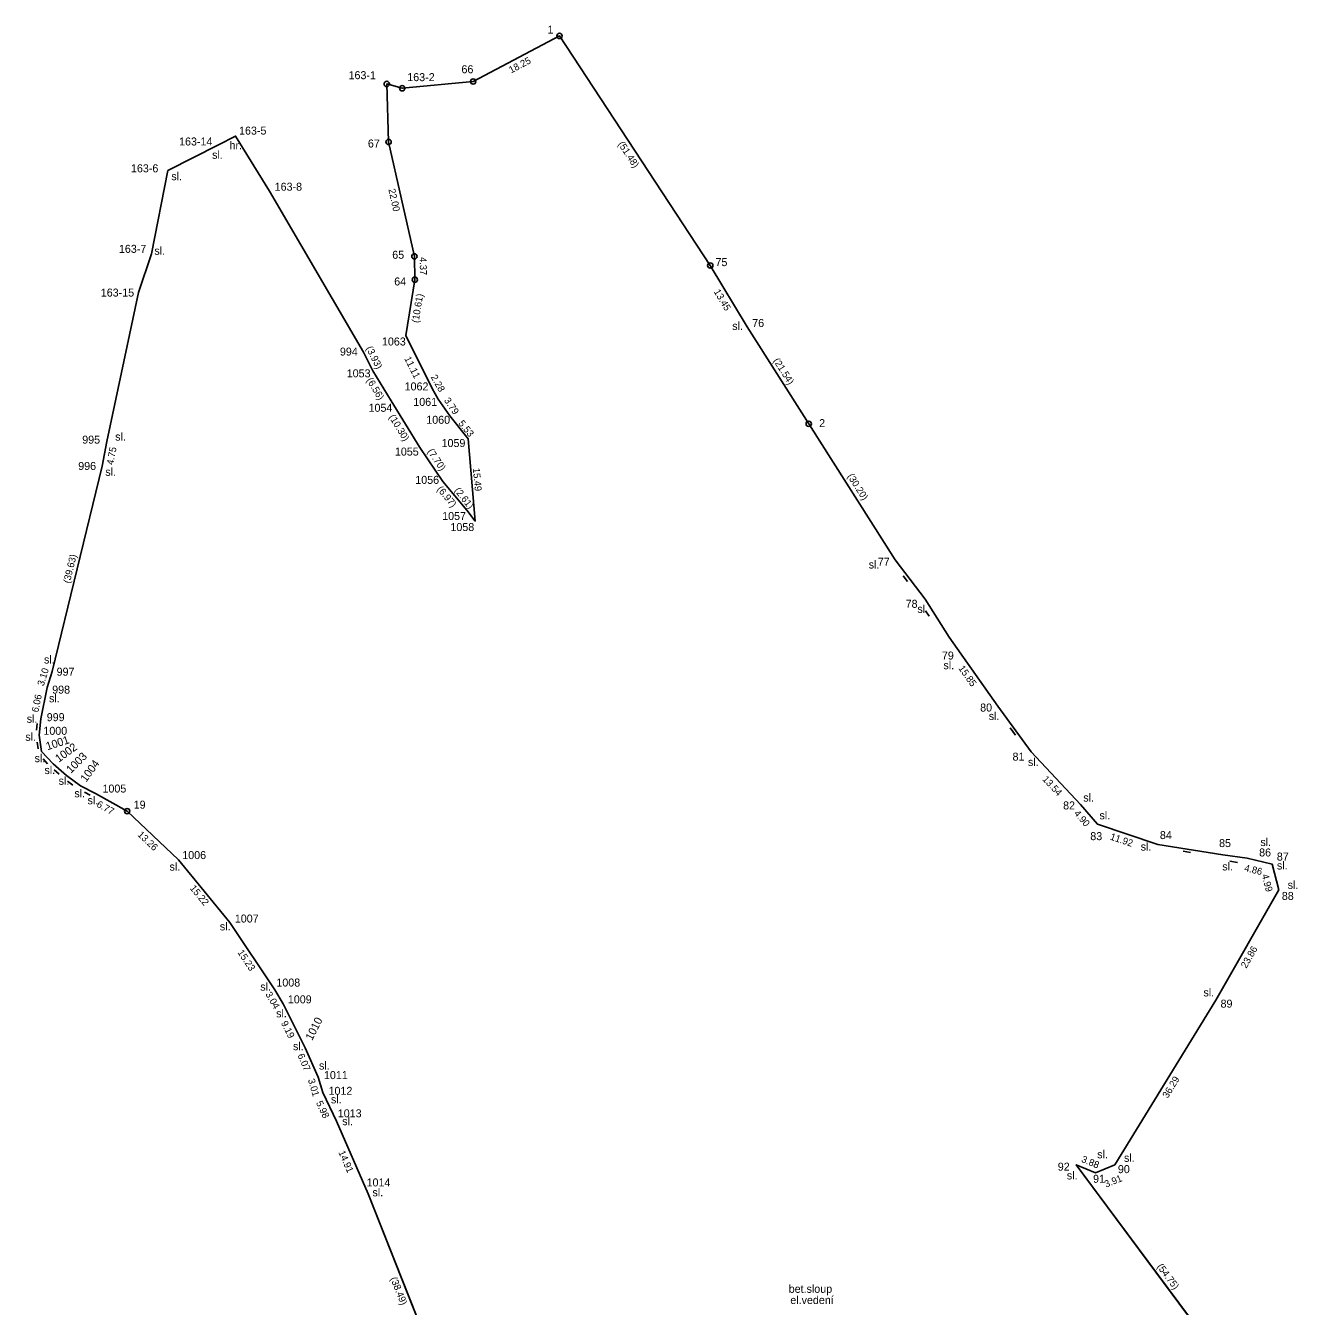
# Model space of a CAD drawing. Extents: x -555170 to -550532, y -1039598 to -1034701.
# Drawn here: x -553164.9 to -552926.5, y -1037844.3 to -1037604.2 of the extents above; entities that cross this region are included whole.
import ezdxf

# ---------------------------------------------------------------- set-up
doc = ezdxf.new("R2010")
doc.units = 0
for name, color, linetype in [('Vrstva 10', 7, 'Continuous'), ('Vrstva 40', 7, 'Continuous'), ('Vrstva 43', 7, 'Continuous'), ('Vrstva 48', 7, 'Continuous')]:
    doc.layers.add(name, color=color, linetype=linetype)

msp = doc.modelspace()

# ---------------------------------------------------------------- linework, layer by layer
at = {"layer": 'Vrstva 10'}
for p, q in [((-553000.41, -1037707.36), (-552999.6, -1037708.41)), ((-552996.24, -1037713.94), (-552995.52, -1037714.93)), ((-553162.87, -1037736.3), (-553162.77, -1037735.08)), ((-552980.37, -1037735.85), (-552979.35, -1037737.26)), ((-553162.6, -1037739.81), (-553162.77, -1037738.59)), ((-553160.85, -1037742.63), (-553161.65, -1037741.7)), ((-553158.66, -1037744.57), (-553159.59, -1037743.77)), ((-553156.08, -1037746.61), (-553157.06, -1037745.87)), ((-553152.81, -1037748.51), (-553153.89, -1037747.93)), ((-552947.95, -1037758.98), (-552946.57, -1037759.25)), ((-552937.73, -1037761.11), (-552939.17, -1037760.84))]:
    msp.add_line(p, q, dxfattribs=at)
at = {"layer": 'Vrstva 40'}
for p, q in [((-553064.84, -1037606.16), (-553081.02, -1037614.69)), ((-553036.58, -1037649.19), (-553064.84, -1037606.16)), ((-553094.34, -1037615.96), (-553097.23, -1037615.16)), ((-553097.23, -1037615.16), (-553096.88, -1037626.02)), ((-553081.02, -1037614.69), (-553094.34, -1037615.96)), ((-553125.58, -1037624.92), (-553128.8, -1037626.55)), ((-553119.24, -1037635.27), (-553125.58, -1037624.92)), ((-553128.8, -1037626.55), (-553138.25, -1037631.4)), ((-553096.88, -1037626.02), (-553092.05, -1037647.49)), ((-553138.25, -1037631.4), (-553141.35, -1037647.01)), ((-553101.57, -1037665.44), (-553119.24, -1037635.27)), ((-553141.35, -1037647.01), (-553143.76, -1037654.28)), ((-553092.05, -1037647.49), (-553091.97, -1037651.86)), ((-553029.69, -1037660.7), (-553036.58, -1037649.19)), ((-553091.97, -1037651.86), (-553093.67, -1037662.33)), ((-553143.76, -1037654.28), (-553149.7, -1037682.18)), ((-553018.13, -1037678.87), (-553029.69, -1037660.7)), ((-553093.67, -1037662.33), (-553088.69, -1037672.27)), ((-553099.81, -1037668.95), (-553101.57, -1037665.44)), ((-553096.39, -1037674.55), (-553099.81, -1037668.95)), ((-553088.69, -1037672.27), (-553087.56, -1037674.26)), ((-553091.01, -1037683.33), (-553096.39, -1037674.55)), ((-553087.56, -1037674.26), (-553085.43, -1037677.4)), ((-553085.43, -1037677.4), (-553081.94, -1037681.68)), ((-553001.91, -1037704.35), (-553018.13, -1037678.87)), ((-553149.7, -1037682.18), (-553150.56, -1037686.84)), ((-553086.69, -1037689.7), (-553091.01, -1037683.33)), ((-553081.94, -1037681.68), (-553080.63, -1037697.11)), ((-553150.56, -1037686.84), (-553159.95, -1037725.34)), ((-553082.23, -1037695.05), (-553086.69, -1037689.7)), ((-553080.63, -1037697.11), (-553082.23, -1037695.05)), ((-552996.27, -1037711.74), (-553001.91, -1037704.35)), ((-552991.81, -1037718.9), (-552996.27, -1037711.74)), ((-552982.64, -1037731.83), (-552991.81, -1037718.9)), ((-553159.95, -1037725.34), (-553160.87, -1037728.3)), ((-553160.87, -1037728.3), (-553162.1, -1037734.2)), ((-552976.44, -1037740.39), (-552982.64, -1037731.83)), ((-553162.1, -1037734.2), (-553162.4, -1037737.27)), ((-553162.4, -1037737.27), (-553161.93, -1037740.33)), ((-553161.93, -1037740.33), (-553159.79, -1037742.65)), ((-552967.16, -1037750.24), (-552976.44, -1037740.39)), ((-553159.79, -1037742.65), (-553157.27, -1037744.81)), ((-553157.27, -1037744.81), (-553154.67, -1037746.73)), ((-553154.67, -1037746.73), (-553151.83, -1037748.2)), ((-553151.83, -1037748.2), (-553145.9, -1037751.5)), ((-552963.99, -1037753.94), (-552967.16, -1037750.24)), ((-553145.9, -1037751.5), (-553136.29, -1037760.64)), ((-552952.7, -1037757.75), (-552963.99, -1037753.94)), ((-552940.48, -1037759.68), (-552952.7, -1037757.75)), ((-552935.91, -1037760.31), (-552940.48, -1037759.68)), ((-552931.21, -1037761.44), (-552935.91, -1037760.31)), ((-553136.29, -1037760.64), (-553126.62, -1037772.37)), ((-552929.97, -1037766.27), (-552931.21, -1037761.44)), ((-552941.8, -1037786.93), (-552929.97, -1037766.27)), ((-553126.62, -1037772.37), (-553118.18, -1037785.01)), ((-553118.18, -1037785.01), (-553116.65, -1037787.63)), ((-553116.65, -1037787.63), (-553112.53, -1037795.84)), ((-552960.76, -1037817.81), (-552941.8, -1037786.93)), ((-553112.53, -1037795.84), (-553110.07, -1037801.39)), ((-553110.07, -1037801.39), (-553109.23, -1037804.23)), ((-553109.23, -1037804.23), (-553106.68, -1037809.64)), ((-553106.68, -1037809.64), (-553100.71, -1037823.27)), ((-552935.31, -1037861.75), (-552967.96, -1037817.8)), ((-552967.96, -1037817.8), (-552964.38, -1037819.29)), ((-552964.38, -1037819.29), (-552960.76, -1037817.81)), ((-553100.71, -1037823.27), (-553086.52, -1037859.05))]:
    msp.add_line(p, q, dxfattribs=at)
at = {"layer": 'Vrstva 43'}
for p, q in [((-553064.84, -1037606.16), (-553064.84, -1037606.16)), ((-553097.23, -1037615.16), (-553097.23, -1037615.16)), ((-553094.34, -1037615.96), (-553094.34, -1037615.96)), ((-553081.02, -1037614.69), (-553081.02, -1037614.69)), ((-553125.58, -1037624.92), (-553125.58, -1037624.92)), ((-553128.8, -1037626.55), (-553128.8, -1037626.55)), ((-553096.88, -1037626.02), (-553096.88, -1037626.02)), ((-553138.25, -1037631.4), (-553138.25, -1037631.4)), ((-553119.24, -1037635.27), (-553119.24, -1037635.27)), ((-553141.35, -1037647.01), (-553141.35, -1037647.01)), ((-553092.05, -1037647.49), (-553092.05, -1037647.49)), ((-553036.58, -1037649.19), (-553036.58, -1037649.19)), ((-553091.97, -1037651.86), (-553091.97, -1037651.86)), ((-553143.76, -1037654.28), (-553143.76, -1037654.28)), ((-553029.69, -1037660.7), (-553029.69, -1037660.7)), ((-553093.67, -1037662.33), (-553093.67, -1037662.33)), ((-553101.57, -1037665.44), (-553101.57, -1037665.44)), ((-553099.81, -1037668.95), (-553099.81, -1037668.95)), ((-553088.69, -1037672.27), (-553088.69, -1037672.27)), ((-553096.39, -1037674.55), (-553096.39, -1037674.55)), ((-553087.56, -1037674.26), (-553087.56, -1037674.26)), ((-553085.43, -1037677.4), (-553085.43, -1037677.4)), ((-553018.13, -1037678.87), (-553018.13, -1037678.87)), ((-553149.7, -1037682.18), (-553149.7, -1037682.18)), ((-553091.01, -1037683.33), (-553091.01, -1037683.33)), ((-553081.94, -1037681.68), (-553081.94, -1037681.68)), ((-553150.56, -1037686.84), (-553150.56, -1037686.84)), ((-553086.69, -1037689.7), (-553086.69, -1037689.7)), ((-553082.23, -1037695.05), (-553082.23, -1037695.05)), ((-553080.63, -1037697.11), (-553080.63, -1037697.11)), ((-553001.91, -1037704.35), (-553001.91, -1037704.35)), ((-552996.27, -1037711.74), (-552996.27, -1037711.74)), ((-552991.81, -1037718.9), (-552991.81, -1037718.9)), ((-553159.95, -1037725.34), (-553159.95, -1037725.34)), ((-553160.87, -1037728.3), (-553160.87, -1037728.3)), ((-552982.64, -1037731.83), (-552982.64, -1037731.83)), ((-553162.1, -1037734.2), (-553162.1, -1037734.2)), ((-553162.4, -1037737.27), (-553162.4, -1037737.27)), ((-553161.93, -1037740.33), (-553161.93, -1037740.33)), ((-552976.44, -1037740.39), (-552976.44, -1037740.39)), ((-553159.79, -1037742.65), (-553159.79, -1037742.65)), ((-553157.27, -1037744.81), (-553157.27, -1037744.81)), ((-553154.67, -1037746.73), (-553154.67, -1037746.73)), ((-553151.83, -1037748.2), (-553151.83, -1037748.2)), ((-552967.16, -1037750.24), (-552967.16, -1037750.24)), ((-553145.9, -1037751.5), (-553145.9, -1037751.5)), ((-552963.99, -1037753.94), (-552963.99, -1037753.94)), ((-552952.7, -1037757.75), (-552952.7, -1037757.75)), ((-552940.48, -1037759.68), (-552940.48, -1037759.68)), ((-552935.91, -1037760.31), (-552935.91, -1037760.31)), ((-553136.29, -1037760.64), (-553136.29, -1037760.64)), ((-552931.21, -1037761.44), (-552931.21, -1037761.44)), ((-552929.97, -1037766.27), (-552929.97, -1037766.27)), ((-553126.62, -1037772.37), (-553126.62, -1037772.37)), ((-553118.18, -1037785.01), (-553118.18, -1037785.01)), ((-553116.65, -1037787.63), (-553116.65, -1037787.63)), ((-552941.8, -1037786.93), (-552941.8, -1037786.93)), ((-553112.53, -1037795.84), (-553112.53, -1037795.84)), ((-553110.07, -1037801.39), (-553110.07, -1037801.39)), ((-553109.23, -1037804.23), (-553109.23, -1037804.23)), ((-553106.68, -1037809.64), (-553106.68, -1037809.64)), ((-552967.96, -1037817.8), (-552967.96, -1037817.8)), ((-552960.76, -1037817.81), (-552960.76, -1037817.81)), ((-552964.38, -1037819.29), (-552964.38, -1037819.29)), ((-553100.71, -1037823.27), (-553100.71, -1037823.27))]:
    msp.add_line(p, q, dxfattribs=at)
for centre, radius in [((-553064.84, -1037606.16), 0.5), ((-553064.84, -1037606.16), 0.01), ((-553097.23, -1037615.16), 0.5), ((-553097.23, -1037615.16), 0.01), ((-553094.34, -1037615.96), 0.5), ((-553094.34, -1037615.96), 0.01), ((-553081.02, -1037614.69), 0.5), ((-553081.02, -1037614.69), 0.01), ((-553096.88, -1037626.02), 0.5), ((-553096.88, -1037626.02), 0.01), ((-553092.05, -1037647.49), 0.5), ((-553092.05, -1037647.49), 0.01), ((-553036.58, -1037649.19), 0.5), ((-553036.58, -1037649.19), 0.01), ((-553091.97, -1037651.86), 0.5), ((-553091.97, -1037651.86), 0.01), ((-553018.13, -1037678.87), 0.5), ((-553018.13, -1037678.87), 0.01), ((-553145.9, -1037751.5), 0.5), ((-553145.9, -1037751.5), 0.01)]:
    msp.add_circle(centre, radius, dxfattribs=at)
at = {"layer": 'Vrstva 48'}
for points in [[(-553128.8, -1037626.55), (-553125.58, -1037624.92), (-553119.24, -1037635.27), (-553101.57, -1037665.44), (-553099.81, -1037668.95), (-553096.39, -1037674.55), (-553091.01, -1037683.33), (-553086.69, -1037689.7), (-553082.23, -1037695.05), (-553080.63, -1037697.11), (-553081.94, -1037681.68), (-553085.43, -1037677.4), (-553087.56, -1037674.26), (-553088.69, -1037672.27), (-553093.67, -1037662.33), (-553091.97, -1037651.86), (-553092.05, -1037647.49), (-553096.88, -1037626.02), (-553097.23, -1037615.16), (-553094.34, -1037615.96), (-553081.02, -1037614.69), (-553064.84, -1037606.16), (-553036.58, -1037649.19), (-553029.69, -1037660.7), (-553018.13, -1037678.87), (-553001.91, -1037704.35), (-552996.27, -1037711.74), (-552991.81, -1037718.9), (-552982.64, -1037731.83), (-552976.44, -1037740.39), (-552967.16, -1037750.24), (-552963.99, -1037753.94), (-552952.7, -1037757.75), (-552940.48, -1037759.68), (-552935.91, -1037760.31), (-552931.21, -1037761.44), (-552929.97, -1037766.27), (-552941.8, -1037786.93), (-552960.76, -1037817.81), (-552964.38, -1037819.29), (-552967.96, -1037817.8), (-552935.31, -1037861.75)], [(-553086.52, -1037859.05), (-553100.71, -1037823.27), (-553106.68, -1037809.64), (-553109.23, -1037804.23), (-553110.07, -1037801.39), (-553112.53, -1037795.84), (-553116.65, -1037787.63), (-553118.18, -1037785.01), (-553126.62, -1037772.37), (-553136.29, -1037760.64), (-553145.9, -1037751.5), (-553151.83, -1037748.2), (-553154.67, -1037746.73), (-553157.27, -1037744.81), (-553159.79, -1037742.65), (-553161.93, -1037740.33), (-553162.4, -1037737.27), (-553162.1, -1037734.2), (-553160.87, -1037728.3), (-553159.95, -1037725.34), (-553150.56, -1037686.84), (-553149.7, -1037682.18), (-553143.76, -1037654.28), (-553141.35, -1037647.01), (-553138.25, -1037631.4), (-553128.8, -1037626.55)]]:
    msp.add_lwpolyline(points, dxfattribs=at)

# ---------------------------------------------------------------- texts
at = {"layer": 'Vrstva 10'}
for s, rotation, p in [('18.25', 27.7956, (-553073.91, -1037613.2)), ('(51.48)', 303.2962, (-553053.93, -1037626.42)), ('22.00', 282.6788, (-553096.93, -1037634.93)), ('4.37', 271.0488, (-553091.06, -1037647.63)), ('(10.61)', 80.7774, (-553091.27, -1037660.02)), ('13.45', 300.9052, (-553035.97, -1037654.1)), ('(3.93)', 296.6303, (-553101.16, -1037664.69)), ('11.11', 296.6111, (-553093.98, -1037666.62)), ('(21.54)', 302.4737, (-553024.83, -1037667.03)), ('(6.56)', 301.413, (-553101.09, -1037670.69)), ('2.28', 299.5896, (-553089.03, -1037670.1)), ('3.79', 304.1508, (-553086.56, -1037674.49)), ('(10.30)', 301.4981, (-553096.88, -1037677.58)), ('5.53', 309.1945, (-553083.9, -1037678.84)), ('4.75', 79.5437, (-553148.49, -1037686.66)), ('(7.70)', 304.1443, (-553089.67, -1037684.06)), ('15.49', 274.8527, (-553081.08, -1037687.21)), ('(30.20)', 302.4737, (-553010.93, -1037688.7)), ('(6.97)', 309.8161, (-553087.9, -1037691.18)), ('(2.61)', 307.8364, (-553084.62, -1037691.39)), ('(39.63)', 76.2934, (-553156.65, -1037708.86)), ('15.85', 305.3444, (-552990.12, -1037724.73)), ('3.10', 72.7342, (-553161.55, -1037728.13)), ('6.06', 78.2239, (-553162.57, -1037733.05)), ('13.54', 313.2933, (-552974.41, -1037745.6)), ('6.77', 330.9044, (-553151.75, -1037750.59)), ('4.90', 310.5885, (-552968.48, -1037751.97)), ('13.26', 316.4359, (-553144.04, -1037756.03)), ('11.92', 341.3522, (-552961.72, -1037756.8)), ('4.86', 346.4812, (-552936.56, -1037762.71)), ('4.99', 284.3985, (-552933.2, -1037763.46)), ('15.22', 309.5016, (-553134.22, -1037765.99)), ('23.86', 60.2044, (-552936.08, -1037781.06)), ('15.23', 303.7319, (-553125.27, -1037777.99)), ('3.04', 300.2836, (-553120.03, -1037785.81)), ('9.19', 296.6487, (-553117.1, -1037791.2)), ('6.07', 293.905, (-553114, -1037797.27)), ('3.01', 286.4769, (-553112.02, -1037801.85)), ('36.29', 58.4505, (-552950.81, -1037805.42)), ('5.98', 295.2368, (-553110.53, -1037806.17)), ('14.91', 293.6536, (-553106.32, -1037815.45)), ('3.88', 337.4029, (-552967.12, -1037817.23)), ('3.91', 22.2367, (-552962.37, -1037822.1)), ('(54.75)', 306.6083, (-552952.9, -1037836.9)), ('(38.49)', 291.64, (-553096.57, -1037839.11))]:
    msp.add_text(s, height=1.3, rotation=rotation, dxfattribs=at).set_placement(p)
at = {"layer": 'Vrstva 43'}
for s, p in [('1', (-553067.09, -1037605.72)), ('163-1', (-553104.39, -1037614.26)), ('163-2', (-553093.38, -1037614.63)), ('66', (-553083.22, -1037613.15)), ('163-5', (-553124.92, -1037624.65)), ('163-14', (-553136.16, -1037626.69)), ('hr.', (-553126.71, -1037627.41)), ('67', (-553100.76, -1037627.07)), ('sl.', (-553129.97, -1037629.18)), ('163-6', (-553145.18, -1037631.72)), ('sl.', (-553137.62, -1037633.2)), ('163-8', (-553118.24, -1037635.17)), ('163-7', (-553147.44, -1037646.82)), ('sl.', (-553140.79, -1037647.18)), ('65', (-553096.2, -1037647.93)), ('75', (-553035.6, -1037649.31)), ('64', (-553095.83, -1037652.93)), ('163-15', (-553150.84, -1037655.02)), ('76', (-553028.71, -1037660.72)), ('sl.', (-553032.46, -1037661.27)), ('1063', (-553098.13, -1037664.19)), ('994', (-553106.01, -1037666.08)), ('1053', (-553104.73, -1037670.16)), ('1062', (-553093.88, -1037672.61)), ('1054', (-553100.64, -1037676.62)), ('1061', (-553092.25, -1037675.51)), ('1060', (-553089.82, -1037678.87)), ('2', (-553016.17, -1037679.49)), ('995', (-553154.32, -1037682.59)), ('sl.', (-553148.14, -1037682.03)), ('1055', (-553095.7, -1037684.83)), ('1059', (-553086.95, -1037683.23)), ('996', (-553155.07, -1037687.53)), ('sl.', (-553149.99, -1037688.62)), ('1056', (-553091.88, -1037690.13)), ('1057', (-553086.84, -1037696.91)), ('1058', (-553085.29, -1037698.98)), ('sl.', (-553006.87, -1037706)), ('77', (-553005.17, -1037705.48)), ('78', (-552999.95, -1037713.37)), ('sl.', (-552997.74, -1037714.33)), ('79', (-552993.15, -1037723.07)), ('sl.', (-553161.49, -1037723.82)), ('sl.', (-552992.86, -1037724.88)), ('997', (-553159.12, -1037726.1)), ('998', (-553159.95, -1037729.46)), ('sl.', (-553160.55, -1037731.08)), ('80', (-552985.98, -1037732.82)), ('sl.', (-553164.72, -1037734.92)), ('999', (-553160.97, -1037734.62)), ('sl.', (-552984.37, -1037734.41)), ('1000', (-553161.6, -1037737.18)), ('sl.', (-553164.99, -1037738.3)), ('sl.', (-553163.25, -1037742.31)), ('81', (-552979.91, -1037742.02)), ('sl.', (-553161.4, -1037744.54)), ('sl.', (-552977.02, -1037743.03)), ('sl.', (-553158.74, -1037746.55)), ('sl.', (-553155.79, -1037748.9)), ('1005', (-553150.52, -1037748.01)), ('sl.', (-552966.65, -1037749.7)), ('sl.', (-553153.32, -1037750.21)), ('19', (-553144.67, -1037751.03)), ('82', (-552970.43, -1037751.17)), ('sl.', (-552963.61, -1037753.03)), ('83', (-552965.33, -1037756.93)), ('84', (-552952.28, -1037756.73)), ('sl.', (-552955.89, -1037758.89)), ('85', (-552941.19, -1037758.23)), ('sl.', (-552933.44, -1037758.04)), ('1006', (-553135.56, -1037760.48)), ('86', (-552933.68, -1037759.99)), ('87', (-552930.36, -1037760.76)), ('sl.', (-553137.95, -1037762.65)), ('sl.', (-552940.59, -1037762.61)), ('sl.', (-552930.34, -1037762.43)), ('sl.', (-552928.33, -1037766.07)), ('88', (-552929.42, -1037768.14)), ('sl.', (-553128.52, -1037773.85)), ('1007', (-553125.71, -1037772.38)), ('sl.', (-553120.94, -1037785.15)), ('1008', (-553117.92, -1037784.38)), ('1009', (-553115.77, -1037787.53)), ('sl.', (-552944.12, -1037786.23)), ('89', (-552940.91, -1037788.33)), ('sl.', (-553117.97, -1037790.16)), ('sl.', (-553114.81, -1037796.31)), ('sl.', (-553109.93, -1037799.94)), ('1011', (-553109, -1037801.73)), ('1012', (-553108.14, -1037804.68)), ('sl.', (-553107.69, -1037806.28)), ('1013', (-553106.41, -1037808.9)), ('sl.', (-553105.58, -1037810.37)), ('sl.', (-552964.04, -1037816.57)), ('92', (-552971.43, -1037818.9)), ('90', (-552960.16, -1037819.36)), ('sl.', (-552959.02, -1037817.24)), ('1014', (-553101.01, -1037821.86)), ('sl.', (-552969.73, -1037820.54)), ('91', (-552964.81, -1037821.17)), ('sl.', (-553099.91, -1037823.71)), ('bet.sloup', (-553021.87, -1037841.8)), ('el.vedení', (-553021.57, -1037843.9))]:
    msp.add_text(s, height=1.5, dxfattribs=at).set_placement(p)
for s, rotation, p in [('1001', 18, (-553160.85, -1037740.1)), ('1002', 36, (-553158.72, -1037742.43)), ('1003', 45, (-553156.44, -1037744.52)), ('1004', 54, (-553153.6, -1037746.18)), ('1010', 63, (-553111.23, -1037794.6))]:
    msp.add_text(s, height=1.5, rotation=rotation, dxfattribs=at).set_placement(p)

doc.saveas('drawing.dxf')
